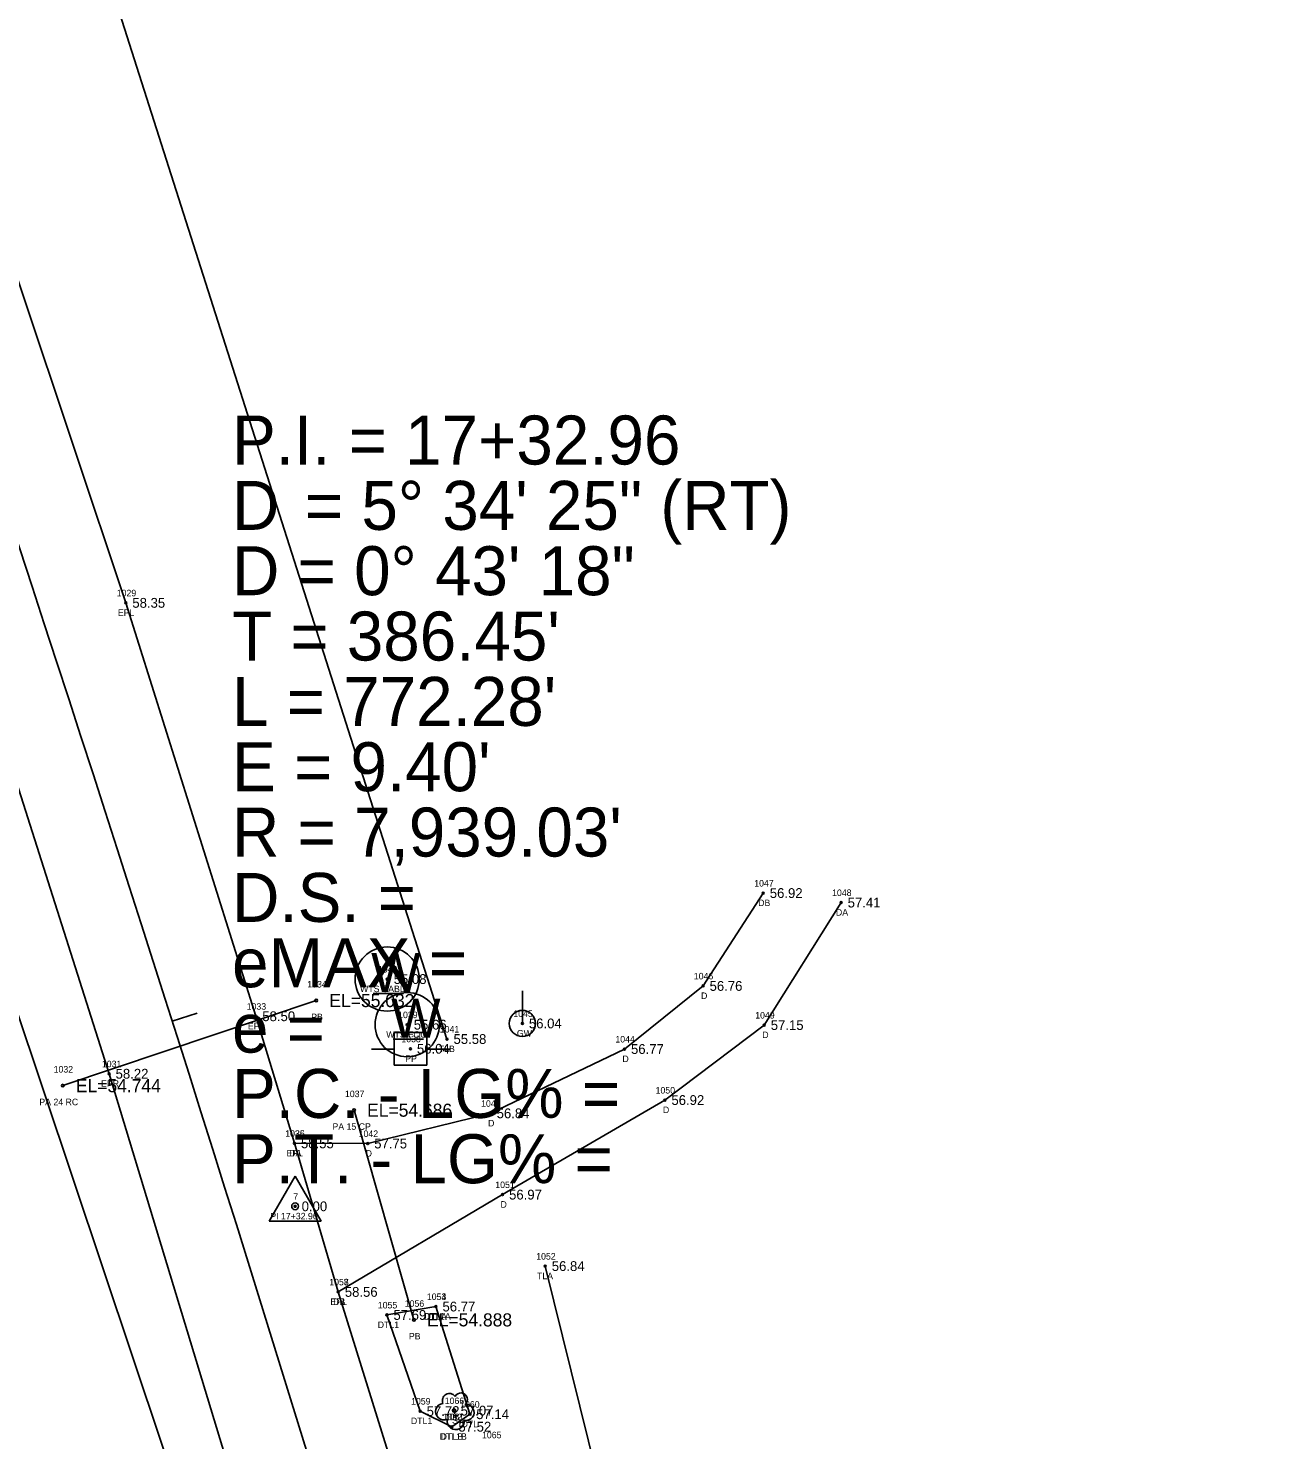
# Model space of a CAD drawing. Extents: x 2396531 to 2397633, y 770203 to 772837.
# Drawn here: x 2396848.8 to 2397041.2, y 771981.7 to 772197.8 of the extents above; entities that cross this region are included whole.
import ezdxf

# ---------------------------------------------------------------- set-up
doc = ezdxf.new("R2010")
doc.units = 0
for name, color, linetype in [('RD_EX_DR_Pipe', 7, 'Continuous'), ('RD_EX_DR_Pipe_txCode', 7, 'Continuous'), ('RD_EX_Driveway', 7, 'Continuous'), ('RD_EX_Driveway_txCode', 7, 'Continuous'), ('RD_EX_H2O', 7, 'Continuous'), ('RD_EX_H2O_txCode', 7, 'Continuous'), ('RD_EX_Road', 7, 'Continuous'), ('RD_EX_Road_txCode', 7, 'Continuous'), ('RD_EX_TX_Driveway_ELEV', 7, 'Continuous'), ('RD_EX_TX_H2O_ELEV', 7, 'Continuous'), ('RD_EX_TX_Road_ELEV', 7, 'Continuous'), ('RD_EX_TX_UT_ELEV', 7, 'Continuous'), ('RD_EX_TX_VEG_ELEV', 7, 'Continuous'), ('RD_EX_UT', 7, 'Continuous'), ('RD_EX_UT_txCode', 7, 'Continuous'), ('RD_EX_VEG', 7, 'Continuous'), ('RD_EX_VEG_txCode', 7, 'Continuous'), ('RD_HC_Cl', 7, 'Continuous'), ('RD_HC_Data', 7, 'Continuous'), ('RD_HC_Data_Tic', 7, 'Continuous'), ('RD_HC_Survey_ELEV', 7, 'Continuous'), ('RD_HC_txCode', 7, 'Continuous'), ('RD_SMD_Locator', 7, 'Continuous'), ('RD_TX_Pipe_ElevEX', 7, 'Continuous')]:
    doc.layers.add(name, color=color, linetype=linetype)

msp = doc.modelspace()

# ---------------------------------------------------------------- linework, layer by layer
at = {"layer": 'RD_EX_DR_Pipe'}
for p, q in [((2396854.1, 772035.94), (2396892.89, 772048.96)), ((2396898.66, 772032.18), (2396907.83, 772000.09))]:
    msp.add_line(p, q, dxfattribs=at)
at = {"layer": 'RD_EX_Driveway'}
for points in [[(2396889.54, 772027.11), (2396900.75, 772027.08), (2396919.48, 772031.7), (2396940.03, 772041.54), (2396952.05, 772051.2), (2396961.26, 772065.41)], [(2396973.17, 772063.96), (2396961.41, 772045.21), (2396946.21, 772033.73), (2396921.38, 772019.26), (2396896.25, 772004.37)]]:
    msp.add_lwpolyline(points, dxfattribs=at)
at = {"layer": 'RD_EX_H2O'}
for points in [[(2396911.19, 772002.13), (2396903.69, 772000.84), (2396908.77, 771986.13), (2396913.63, 771983.74)], [(2396911.19, 772002.13), (2396916.35, 771985.65), (2396913.63, 771983.74)]]:
    msp.add_lwpolyline(points, dxfattribs=at)
at = {"layer": 'RD_EX_Road'}
for points in [[(2396680.92, 772617.84), (2396715.6, 772525.73), (2396750.68, 772430.62), (2396786.3, 772332.21), (2396811.38, 772263.31), (2396839.69, 772181.74), (2396863.75, 772109.83), (2396883.63, 772046.56), (2396889.54, 772027.11), (2396896.25, 772004.37), (2396904.34, 771978.33), (2396908.24, 771964.89), (2396921.74, 771919.68), (2396927.03, 771902.11), (2396950.2, 771821.74), (2396970.47, 771750.68), (2396978.33, 771721.29), (2396990.58, 771675.04), (2397004.94, 771620.49), (2397034.26, 771508.8), (2397061.11, 771410.49), (2397060.64, 771407.04), (2397062.07, 771407.67)], [(2396658.78, 772611.07), (2396693.37, 772516.9), (2396729.65, 772418.78), (2396760.7, 772333.11), (2396788.58, 772254.87), (2396814.65, 772181.57), (2396841.1, 772100.86), (2396861.19, 772037.76), (2396886.09, 771955.71), (2396907.15, 771884.49), (2396928.56, 771811.72), (2396947.65, 771744.09), (2396985.17, 771602.64), (2397011.11, 771504.04), (2397037.95, 771404.25), (2397039, 771401.22)]]:
    msp.add_lwpolyline(points, dxfattribs=at)
at = {"layer": 'RD_EX_UT'}
for p, q in [((2396901.6, 772050.04), (2396906.23, 772050.04)), ((2396924.41, 772045.46), (2396924.41, 772050.46)), ((2396904.67, 772043.07), (2396909.3, 772043.07)), ((2396909.78, 772044.09), (2396904.78, 772044.09)), ((2396904.78, 772044.09), (2396904.78, 772039.09)), ((2396909.78, 772039.09), (2396909.78, 772044.09)), ((2396901.34, 772041.53), (2396904.81, 772041.53)), ((2396909.7, 772041.53), (2396913.34, 772041.53)), ((2396904.78, 772039.09), (2396909.78, 772039.09))]:
    msp.add_line(p, q, dxfattribs=at)
for centre, radius in [((2396903.73, 772052.25), 4.91), ((2396906.8, 772045.27), 4.91), ((2396924.41, 772045.46), 2)]:
    msp.add_circle(centre, radius, dxfattribs=at)
at = {"layer": 'RD_EX_VEG'}
for points in [[(2396718.46, 772629.07), (2396813.42, 772354.87), (2396912.88, 772043.07)], [(2396666.35, 772324.52), (2396746.5, 772348.13), (2396878.43, 771953.6), (2396907.83, 771806.94), (2396910.04, 771736.08), (2396945.43, 771592.11), (2397049.51, 771229.15), (2396980.16, 771221.67)], [(2396927.91, 772008.32), (2396999.71, 771718.21), (2397059.32, 771736.23), (2397119.67, 771755.84)]]:
    msp.add_lwpolyline(points, dxfattribs=at)
msp.add_circle((2396913.97, 771986.2), 0.25, dxfattribs=at)
for centre, radius, start, end in [((2396913.25, 771987.75), 1.08, 34.9763, 204.756), ((2396915.01, 771987.91), 0.995, 308.7626, 152.0467), ((2396912.4, 771986.05), 1.26, 96.4518, 294.734), ((2396915.81, 771985.92), 1.22, 256.5667, 98.1046), ((2396914.21, 771984.61), 1.32, 166.8827, 5.7589)]:
    msp.add_arc(centre, radius, start, end, dxfattribs=at)
at = {"layer": 'RD_HC_Cl'}
msp.add_arc((2389304.02, 769643.48), 7939.03, 14.59125, 20.164785, dxfattribs=at)
at = {"layer": 'RD_HC_Data'}
for p, q in [((2396885.68, 772015.18), (2396889.65, 772022.06)), ((2396889.65, 772022.06), (2396893.62, 772015.18)), ((2396885.68, 772015.18), (2396893.62, 772015.18))]:
    msp.add_line(p, q, dxfattribs=at)
msp.add_circle((2396889.65, 772017.47), 0.529, dxfattribs=at)
at = {"layer": 'RD_HC_Data_Tic'}
msp.add_line((2396870.86, 772045.81), (2396874.67, 772047.02), dxfattribs=at)
at = {"layer": 'RD_SMD_Locator'}
for centre, radius in [((2396863.75, 772109.83), 0.15), ((2396961.26, 772065.41), 0.15), ((2396973.17, 772063.96), 0.15), ((2396903.73, 772052.25), 0.15), ((2396952.05, 772051.2), 0.15), ((2396892.89, 772048.96), 0.2), ((2396883.63, 772046.56), 0.15), ((2396906.8, 772045.27), 0.15), ((2396924.41, 772045.46), 0.15), ((2396961.41, 772045.21), 0.15), ((2396912.88, 772043.07), 0.15), ((2396907.28, 772041.58), 0.15), ((2396940.03, 772041.54), 0.15), ((2396861.19, 772037.76), 0.15), ((2396854.1, 772035.94), 0.2), ((2396898.66, 772032.18), 0.2), ((2396946.21, 772033.73), 0.15), ((2396919.48, 772031.7), 0.15), ((2396889.54, 772027.11), 0.15), ((2396889.54, 772027.11), 0.15), ((2396900.75, 772027.08), 0.15), ((2396921.38, 772019.26), 0.15), ((2396889.65, 772017.47), 0.15), ((2396927.91, 772008.32), 0.15), ((2396896.25, 772004.37), 0.15), ((2396896.25, 772004.37), 0.15), ((2396911.19, 772002.13), 0.15), ((2396911.19, 772002.13), 0.15), ((2396903.69, 772000.84), 0.15), ((2396907.83, 772000.09), 0.2), ((2396908.77, 771986.13), 0.15), ((2396913.97, 771986.2), 0.15), ((2396916.35, 771985.65), 0.15), ((2396913.63, 771983.74), 0.15), ((2396913.63, 771983.74), 0.15)]:
    msp.add_circle(centre, radius, dxfattribs=at)

# ---------------------------------------------------------------- texts
at = {"layer": 'RD_EX_DR_Pipe_txCode'}
for s, p in [('1034', (2396891.51, 772050.96)), ('PB', (2396892.11, 772045.96)), ('1032', (2396852.71, 772037.94)), ('1037', (2396897.27, 772034.18)), ('PA 24 RC', (2396850.52, 772032.94)), ('PA 15 CP', (2396895.36, 772029.18)), ('1056', (2396906.42, 772002.09)), ('PB', (2396907.05, 771997.09))]:
    msp.add_text(s, height=1, dxfattribs=at).set_placement(p)
at = {"layer": 'RD_EX_Driveway_txCode'}
for s, p in [('1047', (2396959.88, 772066.41)), ('1048', (2396971.79, 772064.96)), ('DB', (2396960.48, 772063.41)), ('DA', (2396972.38, 772061.96)), ('1046', (2396950.64, 772052.2)), ('D', (2396951.74, 772049.2)), ('1049', (2396960.03, 772046.21)), ('1044', (2396938.64, 772042.54)), ('D', (2396961.11, 772043.21)), ('D', (2396939.72, 772039.54)), ('1050', (2396944.79, 772034.73)), ('1043', (2396918.1, 772032.7)), ('D', (2396945.91, 772031.73)), ('D', (2396919.17, 772029.7)), ('1036', (2396888.13, 772028.11)), ('1042', (2396899.37, 772028.08)), ('DA', (2396888.74, 772025.11)), ('D', (2396900.44, 772025.08)), ('1051', (2396920.27, 772020.26)), ('D', (2396921.07, 772017.26)), ('1057', (2396894.87, 772005.37)), ('DB', (2396895.47, 772002.37)), ('1065', (2396918.24, 771981.97))]:
    msp.add_text(s, height=1, dxfattribs=at).set_placement(p)
at = {"layer": 'RD_EX_H2O_txCode'}
for s, p in [('1053', (2396909.8, 772003.13)), ('1054', (2396909.8, 772003.13)), ('1055', (2396902.3, 772001.84)), ('DTL1', (2396902.28, 771998.84)), ('DTL1A', (2396909.29, 772000.13)), ('DTLA', (2396909.45, 772000.13)), ('1059', (2396907.39, 771987.13)), ('1060', (2396914.9, 771986.65)), ('DTL1', (2396907.36, 771984.13)), ('1062', (2396912.22, 771984.74)), ('1061', (2396912.51, 771984.74)), ('DTL', (2396915.11, 771983.65)), ('DTL1B', (2396911.75, 771981.74)), ('DTLB', (2396911.91, 771981.74))]:
    msp.add_text(s, height=1, dxfattribs=at).set_placement(p)
at = {"layer": 'RD_EX_Road_txCode'}
for s, p in [('1029', (2396862.36, 772110.83)), ('EPL', (2396862.54, 772107.83)), ('1033', (2396882.24, 772047.56)), ('EPL', (2396882.42, 772044.56)), ('1031', (2396860.09, 772038.76)), ('EPR', (2396859.96, 772035.76)), ('1035', (2396888.15, 772028.11)), ('EPL', (2396888.33, 772025.11)), ('1058', (2396894.87, 772005.37)), ('EPL', (2396895.05, 772002.37))]:
    msp.add_text(s, height=1, dxfattribs=at).set_placement(p)
at = {"layer": 'RD_EX_TX_Driveway_ELEV'}
for s, p in [('56.92', (2396962.26, 772064.66)), ('57.41', (2396974.17, 772063.21)), ('56.76', (2396953.05, 772050.45)), ('57.15', (2396962.41, 772044.46)), ('56.77', (2396941.03, 772040.79)), ('56.92', (2396947.21, 772032.98)), ('56.84', (2396920.48, 772030.95)), ('58.55', (2396890.54, 772026.36)), ('57.75', (2396901.75, 772026.33)), ('56.97', (2396922.38, 772018.51)), ('58.56', (2396897.25, 772003.62))]:
    msp.add_text(s, height=1.5, dxfattribs=at).set_placement(p)
at = {"layer": 'RD_EX_TX_H2O_ELEV'}
for s, p in [('56.77', (2396912.19, 772001.38)), ('56.77', (2396912.19, 772001.38)), ('57.69', (2396904.69, 772000.09)), ('57.72', (2396909.77, 771985.38)), ('57.52', (2396914.63, 771982.99)), ('57.52', (2396914.63, 771982.99)), ('57.14', (2396917.35, 771984.9))]:
    msp.add_text(s, height=1.5, dxfattribs=at).set_placement(p)
at = {"layer": 'RD_EX_TX_Road_ELEV'}
for s, p in [('58.35', (2396864.75, 772109.08)), ('58.50', (2396884.63, 772045.81)), ('58.22', (2396862.19, 772037.01)), ('58.55', (2396890.54, 772026.36)), ('58.56', (2396897.25, 772003.62))]:
    msp.add_text(s, height=1.5, dxfattribs=at).set_placement(p)
at = {"layer": 'RD_EX_TX_UT_ELEV'}
for s, p in [('55.08', (2396904.73, 772051.5)), ('55.66', (2396907.8, 772044.52)), ('56.04', (2396925.41, 772044.71))]:
    msp.add_text(s, height=1.5, dxfattribs=at).set_placement(p)
at = {"layer": 'RD_EX_TX_VEG_ELEV'}
for s, p in [('55.58', (2396913.88, 772042.32)), ('56.84', (2396928.91, 772007.57)), ('57.07', (2396914.97, 771985.45))]:
    msp.add_text(s, height=1.5, dxfattribs=at).set_placement(p)
at = {"layer": 'RD_EX_UT'}
for p in [(2396901.27, 772050.25), (2396904.33, 772043.27)]:
    msp.add_text('W', height=6, dxfattribs=at).set_placement(p)
at = {"layer": 'RD_EX_UT_txCode'}
for s, p in [('1040', (2396902.31, 772053.25)), ('WTS CABLE', (2396899.58, 772050.25)), ('1039', (2396905.41, 772046.27)), ('1045', (2396923.03, 772046.46)), ('WTS FOC', (2396903.59, 772043.27)), ('1038', (2396905.9, 772042.58)), ('GW', (2396923.57, 772043.46)), ('PP', (2396906.5, 772039.58))]:
    msp.add_text(s, height=1, dxfattribs=at).set_placement(p)
at = {"layer": 'RD_EX_VEG_txCode'}
for s, p in [('1041', (2396911.78, 772044.07)), ('TLB', (2396911.63, 772041.07)), ('1052', (2396926.53, 772009.32)), ('TLA', (2396926.65, 772006.32)), ('1066', (2396912.54, 771987.2)), ('S', (2396913.66, 771984.2))]:
    msp.add_text(s, height=1, dxfattribs=at).set_placement(p)
at = {"layer": 'RD_HC_Data'}
for s, p in [('P.I. = 17+32.96', (2396880, 772131)), ('D', (2396880, 772121)), ('    = 5%%d 34\' 25" (RT)', (2396880, 772121)), ('D = 0%%d 43\' 18"', (2396880, 772111)), ("T = 386.45'", (2396880, 772101)), ("L = 772.28'", (2396880, 772091)), ("E = 9.40'", (2396880, 772081)), ("R = 7,939.03'", (2396880, 772071)), ('D.S. = ', (2396880, 772061)), ('eMAX = ', (2396880, 772051)), ('e = ', (2396880, 772041)), ('P.C. - LG% = ', (2396880, 772031)), ('P.T. - LG% = ', (2396880, 772021))]:
    msp.add_text(s, height=7.5, dxfattribs=at).set_placement(p)
at = {"layer": 'RD_HC_Survey_ELEV'}
for s, p in [('56.04', (2396908.28, 772040.83)), ('0.00', (2396890.65, 772016.72))]:
    msp.add_text(s, height=1.5, dxfattribs=at).set_placement(p)
at = {"layer": 'RD_HC_txCode'}
for s, p in [('7', (2396889.37, 772018.47)), ('PI 17+32.96', (2396885.85, 772015.47))]:
    msp.add_text(s, height=1, dxfattribs=at).set_placement(p)
at = {"layer": 'RD_TX_Pipe_ElevEX'}
for s, p in [('EL=55.032', (2396894.89, 772047.96)), ('EL=54.744', (2396856.1, 772034.94)), ('EL=54.686', (2396900.66, 772031.18)), ('EL=54.888', (2396909.83, 771999.09))]:
    msp.add_text(s, height=2, dxfattribs=at).set_placement(p)

doc.saveas('drawing.dxf')
